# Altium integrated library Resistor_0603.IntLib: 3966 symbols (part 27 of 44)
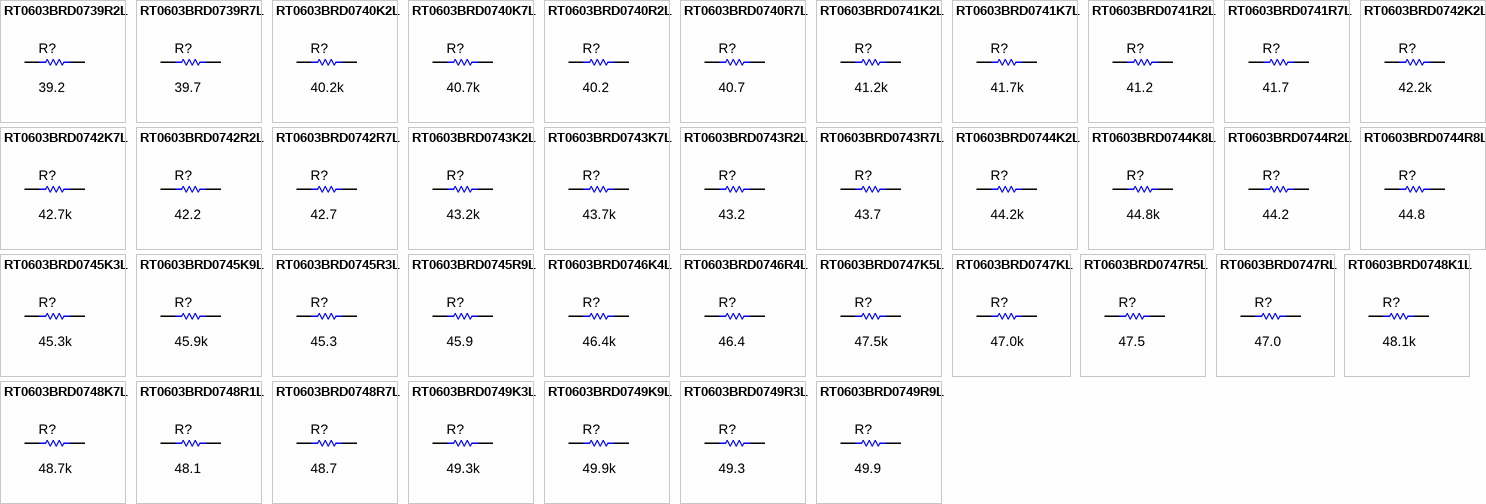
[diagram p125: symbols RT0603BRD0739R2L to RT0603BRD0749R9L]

## RT0603BRD0749R9L
designator R?  ValueDisplayed: 49.9  (hidden comment: RT0603BRD0749R9L)
RES, 49.9, 0.1%, 0.1 W, 0603; Manufacturer: Yageo America; CompType: Resistor; Value: 49.9; Value_Code: 49R9; Tolerance_%: 0.1; Value2: 0.1W; VDC_V: 75; TempCo: 25 ppm/C; SizeArea_mm2: 1.28; SizeX_mm: 1.6; SizeY_mm: 0.8; SizeZ_mm: 1; EIA_Code: E192; U/M: EA; AEC Category: Q200
signal-integrity model Resistor
simulation model Resistor
footprint 0603
footprint 0603M
footprint 0603L
footprint 0603_HV
footprint 0603S
pins: 1, 2

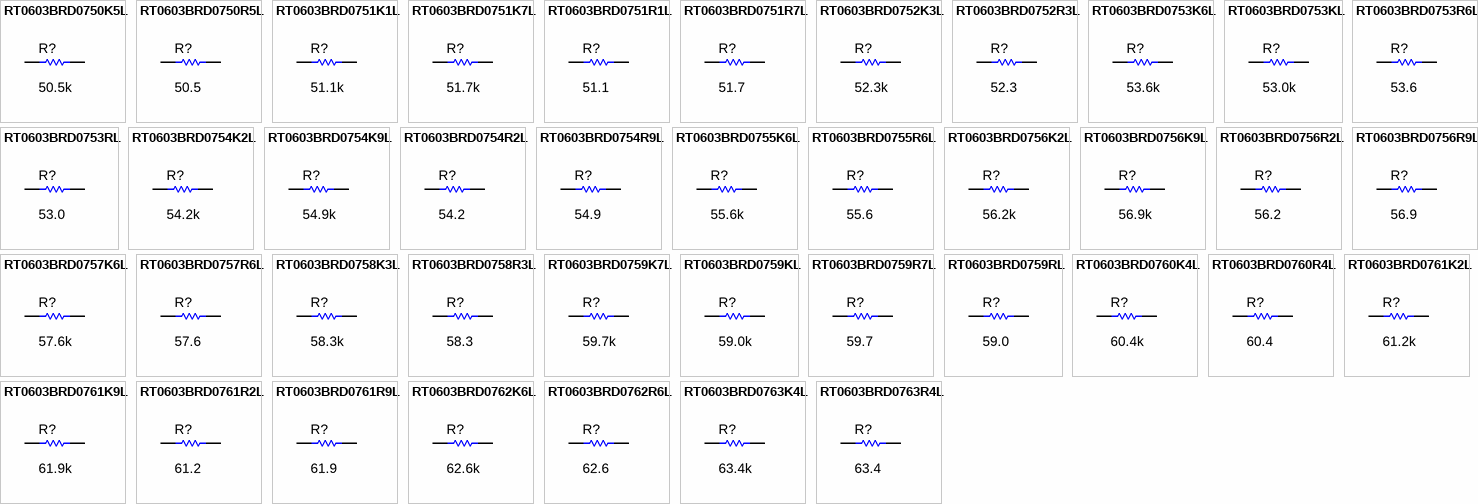
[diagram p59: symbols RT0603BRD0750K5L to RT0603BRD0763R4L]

## RT0603BRD0750K5L
designator R?  ValueDisplayed: 50.5k  (hidden comment: RT0603BRD0750K5L)
RES, 50.5 k, 0.1%, 0.1 W, 0603; Manufacturer: Yageo America; CompType: Resistor; Value: 50.5k; Res_ohm: 50500; Value_Code: 50k5; Tolerance_%: 0.1; Value2: 0.1W; VDC_V: 75; TempCo: 25 ppm/C; SizeArea_mm2: 1.28; SizeX_mm: 1.6; SizeY_mm: 0.8; SizeZ_mm: 1; EIA_Code: E192; U/M: EA; AEC Category: Q200
signal-integrity model Resistor
simulation model Resistor
footprint 0603
footprint 0603M
footprint 0603L
footprint 0603_HV
footprint 0603S
pins: 1, 2

## RT0603BRD0750R5L
designator R?  ValueDisplayed: 50.5  (hidden comment: RT0603BRD0750R5L)
RES, 50.5, 0.1%, 0.1 W, 0603; Manufacturer: Yageo America; CompType: Resistor; Value: 50.5; Value_Code: 50R5; Tolerance_%: 0.1; Value2: 0.1W; VDC_V: 75; TempCo: 25 ppm/C; SizeArea_mm2: 1.28; SizeX_mm: 1.6; SizeY_mm: 0.8; SizeZ_mm: 1; EIA_Code: E192; U/M: EA; AEC Category: Q200
signal-integrity model Resistor
simulation model Resistor
footprint 0603
footprint 0603M
footprint 0603L
footprint 0603_HV
footprint 0603S
pins: 1, 2

## RT0603BRD0751K1L
designator R?  ValueDisplayed: 51.1k  (hidden comment: RT0603BRD0751K1L)
RES, 51.1 k, 0.1%, 0.1 W, 0603; Manufacturer: Yageo America; CompType: Resistor; Value: 51.1k; Res_ohm: 51100; Value_Code: 51k1; Tolerance_%: 0.1; Value2: 0.1W; VDC_V: 75; TempCo: 25 ppm/C; SizeArea_mm2: 1.28; SizeX_mm: 1.6; SizeY_mm: 0.8; SizeZ_mm: 1; EIA_Code: E192; U/M: EA; AEC Category: Q200
signal-integrity model Resistor
simulation model Resistor
footprint 0603
footprint 0603M
footprint 0603L
footprint 0603_HV
footprint 0603S
pins: 1, 2

## RT0603BRD0751K7L
designator R?  ValueDisplayed: 51.7k  (hidden comment: RT0603BRD0751K7L)
RES, 51.7 k, 0.1%, 0.1 W, 0603; Manufacturer: Yageo America; CompType: Resistor; Value: 51.7k; Res_ohm: 51700; Value_Code: 51k7; Tolerance_%: 0.1; Value2: 0.1W; VDC_V: 75; TempCo: 25 ppm/C; SizeArea_mm2: 1.28; SizeX_mm: 1.6; SizeY_mm: 0.8; SizeZ_mm: 1; EIA_Code: E192; U/M: EA; AEC Category: Q200
signal-integrity model Resistor
simulation model Resistor
footprint 0603
footprint 0603M
footprint 0603L
footprint 0603_HV
footprint 0603S
pins: 1, 2

## RT0603BRD0751R1L
designator R?  ValueDisplayed: 51.1  (hidden comment: RT0603BRD0751R1L)
RES, 51.1, 0.1%, 0.1 W, 0603; Manufacturer: Yageo America; CompType: Resistor; Value: 51.1; Value_Code: 51R1; Tolerance_%: 0.1; Value2: 0.1W; VDC_V: 75; TempCo: 25 ppm/C; SizeArea_mm2: 1.28; SizeX_mm: 1.6; SizeY_mm: 0.8; SizeZ_mm: 1; EIA_Code: E192; U/M: EA; AEC Category: Q200; Green_Lifecycle: Active; Green_REACh: Passed
signal-integrity model Resistor
simulation model Resistor
footprint 0603
footprint 0603M
footprint 0603L
footprint 0603_HV
footprint 0603S
pins: 1, 2

## RT0603BRD0751R7L
designator R?  ValueDisplayed: 51.7  (hidden comment: RT0603BRD0751R7L)
RES, 51.7, 0.1%, 0.1 W, 0603; Manufacturer: Yageo America; CompType: Resistor; Value: 51.7; Value_Code: 51R7; Tolerance_%: 0.1; Value2: 0.1W; VDC_V: 75; TempCo: 25 ppm/C; SizeArea_mm2: 1.28; SizeX_mm: 1.6; SizeY_mm: 0.8; SizeZ_mm: 1; EIA_Code: E192; U/M: EA; AEC Category: Q200
signal-integrity model Resistor
simulation model Resistor
footprint 0603
footprint 0603M
footprint 0603L
footprint 0603_HV
footprint 0603S
pins: 1, 2

## RT0603BRD0752K3L
designator R?  ValueDisplayed: 52.3k  (hidden comment: RT0603BRD0752K3L)
RES, 52.3 k, 0.1%, 0.1 W, 0603; Manufacturer: Yageo America; CompType: Resistor; Value: 52.3k; Res_ohm: 52300; Value_Code: 52k3; Tolerance_%: 0.1; Value2: 0.1W; VDC_V: 75; TempCo: 25 ppm/C; SizeArea_mm2: 1.28; SizeX_mm: 1.6; SizeY_mm: 0.8; SizeZ_mm: 1; EIA_Code: E192; U/M: EA; AEC Category: Q200
signal-integrity model Resistor
simulation model Resistor
footprint 0603
footprint 0603M
footprint 0603L
footprint 0603_HV
footprint 0603S
pins: 1, 2

## RT0603BRD0752R3L
designator R?  ValueDisplayed: 52.3  (hidden comment: RT0603BRD0752R3L)
RES, 52.3, 0.1%, 0.1 W, 0603; Manufacturer: Yageo America; CompType: Resistor; Value: 52.3; Value_Code: 52R3; Tolerance_%: 0.1; Value2: 0.1W; VDC_V: 75; TempCo: 25 ppm/C; SizeArea_mm2: 1.28; SizeX_mm: 1.6; SizeY_mm: 0.8; SizeZ_mm: 1; EIA_Code: E192; U/M: EA; AEC Category: Q200
signal-integrity model Resistor
simulation model Resistor
footprint 0603
footprint 0603M
footprint 0603L
footprint 0603_HV
footprint 0603S
pins: 1, 2

## RT0603BRD0753K6L
designator R?  ValueDisplayed: 53.6k  (hidden comment: RT0603BRD0753K6L)
RES, 53.6 k, 0.1%, 0.1 W, 0603; Manufacturer: Yageo America; CompType: Resistor; Value: 53.6k; Res_ohm: 53600; Value_Code: 53k6; Tolerance_%: 0.1; Value2: 0.1W; VDC_V: 75; TempCo: 25 ppm/C; SizeArea_mm2: 1.28; SizeX_mm: 1.6; SizeY_mm: 0.8; SizeZ_mm: 1; EIA_Code: E192; U/M: EA; AEC Category: Q200
signal-integrity model Resistor
simulation model Resistor
footprint 0603
footprint 0603M
footprint 0603L
footprint 0603_HV
footprint 0603S
pins: 1, 2

## RT0603BRD0753KL
designator R?  ValueDisplayed: 53.0k  (hidden comment: RT0603BRD0753KL)
RES, 53.0 k, 0.1%, 0.1 W, 0603; Manufacturer: Yageo America; CompType: Resistor; Value: 53.0k; Res_ohm: 53000; Value_Code: 53k0; Tolerance_%: 0.1; Value2: 0.1W; VDC_V: 75; TempCo: 25 ppm/C; SizeArea_mm2: 1.28; SizeX_mm: 1.6; SizeY_mm: 0.8; SizeZ_mm: 1; EIA_Code: E192; U/M: EA; AEC Category: Q200
signal-integrity model Resistor
simulation model Resistor
footprint 0603
footprint 0603M
footprint 0603L
footprint 0603_HV
footprint 0603S
pins: 1, 2

## RT0603BRD0753R6L
designator R?  ValueDisplayed: 53.6  (hidden comment: RT0603BRD0753R6L)
RES, 53.6, 0.1%, 0.1 W, 0603; Manufacturer: Yageo America; CompType: Resistor; Value: 53.6; Value_Code: 53R6; Tolerance_%: 0.1; Value2: 0.1W; VDC_V: 75; TempCo: 25 ppm/C; SizeArea_mm2: 1.28; SizeX_mm: 1.6; SizeY_mm: 0.8; SizeZ_mm: 1; EIA_Code: E192; U/M: EA; AEC Category: Q200
signal-integrity model Resistor
simulation model Resistor
footprint 0603
footprint 0603M
footprint 0603L
footprint 0603_HV
footprint 0603S
pins: 1, 2

## RT0603BRD0753RL
designator R?  ValueDisplayed: 53.0  (hidden comment: RT0603BRD0753RL)
RES, 53.0, 0.1%, 0.1 W, 0603; Manufacturer: Yageo America; CompType: Resistor; Value: 53.0; Res_ohm: 53; Value_Code: 53R0; Tolerance_%: 0.1; Value2: 0.1W; VDC_V: 75; TempCo: 25 ppm/C; SizeArea_mm2: 1.28; SizeX_mm: 1.6; SizeY_mm: 0.8; SizeZ_mm: 1; EIA_Code: E192; U/M: EA; AEC Category: Q200
signal-integrity model Resistor
simulation model Resistor
footprint 0603
footprint 0603M
footprint 0603L
footprint 0603_HV
footprint 0603S
pins: 1, 2

## RT0603BRD0754K2L
designator R?  ValueDisplayed: 54.2k  (hidden comment: RT0603BRD0754K2L)
RES, 54.2 k, 0.1%, 0.1 W, 0603; Manufacturer: Yageo America; CompType: Resistor; Value: 54.2k; Res_ohm: 54200; Value_Code: 54k2; Tolerance_%: 0.1; Value2: 0.1W; VDC_V: 75; TempCo: 25 ppm/C; SizeArea_mm2: 1.28; SizeX_mm: 1.6; SizeY_mm: 0.8; SizeZ_mm: 1; EIA_Code: E192; U/M: EA; AEC Category: Q200
signal-integrity model Resistor
simulation model Resistor
footprint 0603
footprint 0603M
footprint 0603L
footprint 0603_HV
footprint 0603S
pins: 1, 2

## RT0603BRD0754K9L
designator R?  ValueDisplayed: 54.9k  (hidden comment: RT0603BRD0754K9L)
RES, 54.9 k, 0.1%, 0.1 W, 0603; Manufacturer: Yageo America; CompType: Resistor; Value: 54.9k; Res_ohm: 54900; Value_Code: 54k9; Tolerance_%: 0.1; Value2: 0.1W; VDC_V: 75; TempCo: 25 ppm/C; SizeArea_mm2: 1.28; SizeX_mm: 1.6; SizeY_mm: 0.8; SizeZ_mm: 1; EIA_Code: E192; U/M: EA; AEC Category: Q200
signal-integrity model Resistor
simulation model Resistor
footprint 0603
footprint 0603M
footprint 0603L
footprint 0603_HV
footprint 0603S
pins: 1, 2

## RT0603BRD0754R2L
designator R?  ValueDisplayed: 54.2  (hidden comment: RT0603BRD0754R2L)
RES, 54.2, 0.1%, 0.1 W, 0603; Manufacturer: Yageo America; CompType: Resistor; Value: 54.2; Value_Code: 54R2; Tolerance_%: 0.1; Value2: 0.1W; VDC_V: 75; TempCo: 25 ppm/C; SizeArea_mm2: 1.28; SizeX_mm: 1.6; SizeY_mm: 0.8; SizeZ_mm: 1; EIA_Code: E192; U/M: EA; AEC Category: Q200
signal-integrity model Resistor
simulation model Resistor
footprint 0603
footprint 0603M
footprint 0603L
footprint 0603_HV
footprint 0603S
pins: 1, 2

## RT0603BRD0754R9L
designator R?  ValueDisplayed: 54.9  (hidden comment: RT0603BRD0754R9L)
RES, 54.9, 0.1%, 0.1 W, 0603; Manufacturer: Yageo America; CompType: Resistor; Value: 54.9; Value_Code: 54R9; Tolerance_%: 0.1; Value2: 0.1W; VDC_V: 75; TempCo: 25 ppm/C; SizeArea_mm2: 1.28; SizeX_mm: 1.6; SizeY_mm: 0.8; SizeZ_mm: 1; EIA_Code: E192; U/M: EA; AEC Category: Q200
signal-integrity model Resistor
simulation model Resistor
footprint 0603
footprint 0603M
footprint 0603L
footprint 0603_HV
footprint 0603S
pins: 1, 2

## RT0603BRD0755K6L
designator R?  ValueDisplayed: 55.6k  (hidden comment: RT0603BRD0755K6L)
RES, 55.6 k, 0.1%, 0.1 W, 0603; Manufacturer: Yageo America; CompType: Resistor; Value: 55.6k; Res_ohm: 55600; Value_Code: 55k6; Tolerance_%: 0.1; Value2: 0.1W; VDC_V: 75; TempCo: 25 ppm/C; SizeArea_mm2: 1.28; SizeX_mm: 1.6; SizeY_mm: 0.8; SizeZ_mm: 1; EIA_Code: E192; U/M: EA; AEC Category: Q200
signal-integrity model Resistor
simulation model Resistor
footprint 0603
footprint 0603M
footprint 0603L
footprint 0603_HV
footprint 0603S
pins: 1, 2

## RT0603BRD0755R6L
designator R?  ValueDisplayed: 55.6  (hidden comment: RT0603BRD0755R6L)
RES, 55.6, 0.1%, 0.1 W, 0603; Manufacturer: Yageo America; CompType: Resistor; Value: 55.6; Value_Code: 55R6; Tolerance_%: 0.1; Value2: 0.1W; VDC_V: 75; TempCo: 25 ppm/C; SizeArea_mm2: 1.28; SizeX_mm: 1.6; SizeY_mm: 0.8; SizeZ_mm: 1; EIA_Code: E192; U/M: EA; AEC Category: Q200
signal-integrity model Resistor
simulation model Resistor
footprint 0603
footprint 0603M
footprint 0603L
footprint 0603_HV
footprint 0603S
pins: 1, 2

## RT0603BRD0756K2L
designator R?  ValueDisplayed: 56.2k  (hidden comment: RT0603BRD0756K2L)
RES, 56.2 k, 0.1%, 0.1 W, 0603; Manufacturer: Yageo America; CompType: Resistor; Value: 56.2k; Res_ohm: 56200; Value_Code: 56k2; Tolerance_%: 0.1; Value2: 0.1W; VDC_V: 75; TempCo: 25 ppm/C; SizeArea_mm2: 1.28; SizeX_mm: 1.6; SizeY_mm: 0.8; SizeZ_mm: 1; EIA_Code: E192; U/M: EA; AEC Category: Q200
signal-integrity model Resistor
simulation model Resistor
footprint 0603
footprint 0603M
footprint 0603L
footprint 0603_HV
footprint 0603S
pins: 1, 2

## RT0603BRD0756K9L
designator R?  ValueDisplayed: 56.9k  (hidden comment: RT0603BRD0756K9L)
RES, 56.9 k, 0.1%, 0.1 W, 0603; Manufacturer: Yageo America; CompType: Resistor; Value: 56.9k; Res_ohm: 56900; Value_Code: 56k9; Tolerance_%: 0.1; Value2: 0.1W; VDC_V: 75; TempCo: 25 ppm/C; SizeArea_mm2: 1.28; SizeX_mm: 1.6; SizeY_mm: 0.8; SizeZ_mm: 1; EIA_Code: E192; U/M: EA; AEC Category: Q200
signal-integrity model Resistor
simulation model Resistor
footprint 0603
footprint 0603M
footprint 0603L
footprint 0603_HV
footprint 0603S
pins: 1, 2

## RT0603BRD0756R2L
designator R?  ValueDisplayed: 56.2  (hidden comment: RT0603BRD0756R2L)
RES, 56.2, 0.1%, 0.1 W, 0603; Manufacturer: Yageo America; CompType: Resistor; Value: 56.2; Value_Code: 56R2; Tolerance_%: 0.1; Value2: 0.1W; VDC_V: 75; TempCo: 25 ppm/C; SizeArea_mm2: 1.28; SizeX_mm: 1.6; SizeY_mm: 0.8; SizeZ_mm: 1; EIA_Code: E192; U/M: EA; AEC Category: Q200
signal-integrity model Resistor
simulation model Resistor
footprint 0603
footprint 0603M
footprint 0603L
footprint 0603_HV
footprint 0603S
pins: 1, 2

## RT0603BRD0756R9L
designator R?  ValueDisplayed: 56.9  (hidden comment: RT0603BRD0756R9L)
RES, 56.9, 0.1%, 0.1 W, 0603; Manufacturer: Yageo America; CompType: Resistor; Value: 56.9; Value_Code: 56R9; Tolerance_%: 0.1; Value2: 0.1W; VDC_V: 75; TempCo: 25 ppm/C; SizeArea_mm2: 1.28; SizeX_mm: 1.6; SizeY_mm: 0.8; SizeZ_mm: 1; EIA_Code: E192; U/M: EA; AEC Category: Q200
signal-integrity model Resistor
simulation model Resistor
footprint 0603
footprint 0603M
footprint 0603L
footprint 0603_HV
footprint 0603S
pins: 1, 2

## RT0603BRD0757K6L
designator R?  ValueDisplayed: 57.6k  (hidden comment: RT0603BRD0757K6L)
RES, 57.6 k, 0.1%, 0.1 W, 0603; Manufacturer: Yageo America; CompType: Resistor; Value: 57.6k; Res_ohm: 57600; Value_Code: 57k6; Tolerance_%: 0.1; Value2: 0.1W; VDC_V: 75; TempCo: 25 ppm/C; SizeArea_mm2: 1.28; SizeX_mm: 1.6; SizeY_mm: 0.8; SizeZ_mm: 1; EIA_Code: E192; U/M: EA; AEC Category: Q200
signal-integrity model Resistor
simulation model Resistor
footprint 0603
footprint 0603M
footprint 0603L
footprint 0603_HV
footprint 0603S
pins: 1, 2

## RT0603BRD0757R6L
designator R?  ValueDisplayed: 57.6  (hidden comment: RT0603BRD0757R6L)
RES, 57.6, 0.1%, 0.1 W, 0603; Manufacturer: Yageo America; CompType: Resistor; Value: 57.6; Value_Code: 57R6; Tolerance_%: 0.1; Value2: 0.1W; VDC_V: 75; TempCo: 25 ppm/C; SizeArea_mm2: 1.28; SizeX_mm: 1.6; SizeY_mm: 0.8; SizeZ_mm: 1; EIA_Code: E192; U/M: EA; AEC Category: Q200
signal-integrity model Resistor
simulation model Resistor
footprint 0603
footprint 0603M
footprint 0603L
footprint 0603_HV
footprint 0603S
pins: 1, 2

## RT0603BRD0758K3L
designator R?  ValueDisplayed: 58.3k  (hidden comment: RT0603BRD0758K3L)
RES, 58.3 k, 0.1%, 0.1 W, 0603; Manufacturer: Yageo America; CompType: Resistor; Value: 58.3k; Res_ohm: 58300; Value_Code: 58k3; Tolerance_%: 0.1; Value2: 0.1W; VDC_V: 75; TempCo: 25 ppm/C; SizeArea_mm2: 1.28; SizeX_mm: 1.6; SizeY_mm: 0.8; SizeZ_mm: 1; EIA_Code: E192; U/M: EA; AEC Category: Q200
signal-integrity model Resistor
simulation model Resistor
footprint 0603
footprint 0603M
footprint 0603L
footprint 0603_HV
footprint 0603S
pins: 1, 2

## RT0603BRD0758R3L
designator R?  ValueDisplayed: 58.3  (hidden comment: RT0603BRD0758R3L)
RES, 58.3, 0.1%, 0.1 W, 0603; Manufacturer: Yageo America; CompType: Resistor; Value: 58.3; Value_Code: 58R3; Tolerance_%: 0.1; Value2: 0.1W; VDC_V: 75; TempCo: 25 ppm/C; SizeArea_mm2: 1.28; SizeX_mm: 1.6; SizeY_mm: 0.8; SizeZ_mm: 1; EIA_Code: E192; U/M: EA; AEC Category: Q200
signal-integrity model Resistor
simulation model Resistor
footprint 0603
footprint 0603M
footprint 0603L
footprint 0603_HV
footprint 0603S
pins: 1, 2

## RT0603BRD0759K7L
designator R?  ValueDisplayed: 59.7k  (hidden comment: RT0603BRD0759K7L)
RES, 59.7 k, 0.1%, 0.1 W, 0603; Manufacturer: Yageo America; CompType: Resistor; Value: 59.7k; Res_ohm: 59700; Value_Code: 59k7; Tolerance_%: 0.1; Value2: 0.1W; VDC_V: 75; TempCo: 25 ppm/C; SizeArea_mm2: 1.28; SizeX_mm: 1.6; SizeY_mm: 0.8; SizeZ_mm: 1; EIA_Code: E192; U/M: EA; AEC Category: Q200
signal-integrity model Resistor
simulation model Resistor
footprint 0603
footprint 0603M
footprint 0603L
footprint 0603_HV
footprint 0603S
pins: 1, 2

## RT0603BRD0759KL
designator R?  ValueDisplayed: 59.0k  (hidden comment: RT0603BRD0759KL)
RES, 59.0 k, 0.1%, 0.1 W, 0603; Manufacturer: Yageo America; CompType: Resistor; Value: 59.0k; Res_ohm: 59000; Value_Code: 59k0; Tolerance_%: 0.1; Value2: 0.1W; VDC_V: 75; TempCo: 25 ppm/C; SizeArea_mm2: 1.28; SizeX_mm: 1.6; SizeY_mm: 0.8; SizeZ_mm: 1; EIA_Code: E192; U/M: EA; AEC Category: Q200
signal-integrity model Resistor
simulation model Resistor
footprint 0603
footprint 0603M
footprint 0603L
footprint 0603_HV
footprint 0603S
pins: 1, 2

## RT0603BRD0759R7L
designator R?  ValueDisplayed: 59.7  (hidden comment: RT0603BRD0759R7L)
RES, 59.7, 0.1%, 0.1 W, 0603; Manufacturer: Yageo America; CompType: Resistor; Value: 59.7; Value_Code: 59R7; Tolerance_%: 0.1; Value2: 0.1W; VDC_V: 75; TempCo: 25 ppm/C; SizeArea_mm2: 1.28; SizeX_mm: 1.6; SizeY_mm: 0.8; SizeZ_mm: 1; EIA_Code: E192; U/M: EA; AEC Category: Q200
signal-integrity model Resistor
simulation model Resistor
footprint 0603
footprint 0603M
footprint 0603L
footprint 0603_HV
footprint 0603S
pins: 1, 2

## RT0603BRD0759RL
designator R?  ValueDisplayed: 59.0  (hidden comment: RT0603BRD0759RL)
RES, 59.0, 0.1%, 0.1 W, 0603; Manufacturer: Yageo America; CompType: Resistor; Value: 59.0; Res_ohm: 59; Value_Code: 59R0; Tolerance_%: 0.1; Value2: 0.1W; VDC_V: 75; TempCo: 25 ppm/C; SizeArea_mm2: 1.28; SizeX_mm: 1.6; SizeY_mm: 0.8; SizeZ_mm: 1; EIA_Code: E192; U/M: EA; AEC Category: Q200
signal-integrity model Resistor
simulation model Resistor
footprint 0603
footprint 0603M
footprint 0603L
footprint 0603_HV
footprint 0603S
pins: 1, 2

## RT0603BRD0760K4L
designator R?  ValueDisplayed: 60.4k  (hidden comment: RT0603BRD0760K4L)
RES, 60.4 k, 0.1%, 0.1 W, 0603; Manufacturer: Yageo America; CompType: Resistor; Value: 60.4k; Res_ohm: 60400; Value_Code: 60k4; Tolerance_%: 0.1; Value2: 0.1W; VDC_V: 75; TempCo: 25 ppm/C; SizeArea_mm2: 1.28; SizeX_mm: 1.6; SizeY_mm: 0.8; SizeZ_mm: 1; EIA_Code: E192; U/M: EA; AEC Category: Q200
signal-integrity model Resistor
simulation model Resistor
footprint 0603
footprint 0603M
footprint 0603L
footprint 0603_HV
footprint 0603S
pins: 1, 2

## RT0603BRD0760R4L
designator R?  ValueDisplayed: 60.4  (hidden comment: RT0603BRD0760R4L)
RES, 60.4, 0.1%, 0.1 W, 0603; Manufacturer: Yageo America; CompType: Resistor; Value: 60.4; Value_Code: 60R4; Tolerance_%: 0.1; Value2: 0.1W; VDC_V: 75; TempCo: 25 ppm/C; SizeArea_mm2: 1.28; SizeX_mm: 1.6; SizeY_mm: 0.8; SizeZ_mm: 1; EIA_Code: E192; U/M: EA; AEC Category: Q200
signal-integrity model Resistor
simulation model Resistor
footprint 0603
footprint 0603M
footprint 0603L
footprint 0603_HV
footprint 0603S
pins: 1, 2

## RT0603BRD0761K2L
designator R?  ValueDisplayed: 61.2k  (hidden comment: RT0603BRD0761K2L)
RES, 61.2 k, 0.1%, 0.1 W, 0603; Manufacturer: Yageo America; CompType: Resistor; Value: 61.2k; Res_ohm: 61200; Value_Code: 61k2; Tolerance_%: 0.1; Value2: 0.1W; VDC_V: 75; TempCo: 25 ppm/C; SizeArea_mm2: 1.28; SizeX_mm: 1.6; SizeY_mm: 0.8; SizeZ_mm: 1; EIA_Code: E192; U/M: EA; AEC Category: Q200
signal-integrity model Resistor
simulation model Resistor
footprint 0603
footprint 0603M
footprint 0603L
footprint 0603_HV
footprint 0603S
pins: 1, 2

## RT0603BRD0761K9L
designator R?  ValueDisplayed: 61.9k  (hidden comment: RT0603BRD0761K9L)
RES, 61.9 k, 0.1%, 0.1 W, 0603; Manufacturer: Yageo America; CompType: Resistor; Value: 61.9k; Res_ohm: 61900; Value_Code: 61k9; Tolerance_%: 0.1; Value2: 0.1W; VDC_V: 75; TempCo: 25 ppm/C; SizeArea_mm2: 1.28; SizeX_mm: 1.6; SizeY_mm: 0.8; SizeZ_mm: 1; EIA_Code: E192; U/M: EA; AEC Category: Q200
signal-integrity model Resistor
simulation model Resistor
footprint 0603
footprint 0603M
footprint 0603L
footprint 0603_HV
footprint 0603S
pins: 1, 2

## RT0603BRD0761R2L
designator R?  ValueDisplayed: 61.2  (hidden comment: RT0603BRD0761R2L)
RES, 61.2, 0.1%, 0.1 W, 0603; Manufacturer: Yageo America; CompType: Resistor; Value: 61.2; Value_Code: 61R2; Tolerance_%: 0.1; Value2: 0.1W; VDC_V: 75; TempCo: 25 ppm/C; SizeArea_mm2: 1.28; SizeX_mm: 1.6; SizeY_mm: 0.8; SizeZ_mm: 1; EIA_Code: E192; U/M: EA; AEC Category: Q200
signal-integrity model Resistor
simulation model Resistor
footprint 0603
footprint 0603M
footprint 0603L
footprint 0603_HV
footprint 0603S
pins: 1, 2

## RT0603BRD0761R9L
designator R?  ValueDisplayed: 61.9  (hidden comment: RT0603BRD0761R9L)
RES, 61.9, 0.1%, 0.1 W, 0603; Manufacturer: Yageo America; CompType: Resistor; Value: 61.9; Value_Code: 61R9; Tolerance_%: 0.1; Value2: 0.1W; VDC_V: 75; TempCo: 25 ppm/C; SizeArea_mm2: 1.28; SizeX_mm: 1.6; SizeY_mm: 0.8; SizeZ_mm: 1; EIA_Code: E192; U/M: EA; AEC Category: Q200
signal-integrity model Resistor
simulation model Resistor
footprint 0603
footprint 0603M
footprint 0603L
footprint 0603_HV
footprint 0603S
pins: 1, 2

## RT0603BRD0762K6L
designator R?  ValueDisplayed: 62.6k  (hidden comment: RT0603BRD0762K6L)
RES, 62.6 k, 0.1%, 0.1 W, 0603; Manufacturer: Yageo America; CompType: Resistor; Value: 62.6k; Res_ohm: 62600; Value_Code: 62k6; Tolerance_%: 0.1; Value2: 0.1W; VDC_V: 75; TempCo: 25 ppm/C; SizeArea_mm2: 1.28; SizeX_mm: 1.6; SizeY_mm: 0.8; SizeZ_mm: 1; EIA_Code: E192; U/M: EA; AEC Category: Q200
signal-integrity model Resistor
simulation model Resistor
footprint 0603
footprint 0603M
footprint 0603L
footprint 0603_HV
footprint 0603S
pins: 1, 2

## RT0603BRD0762R6L
designator R?  ValueDisplayed: 62.6  (hidden comment: RT0603BRD0762R6L)
RES, 62.6, 0.1%, 0.1 W, 0603; Manufacturer: Yageo America; CompType: Resistor; Value: 62.6; Value_Code: 62R6; Tolerance_%: 0.1; Value2: 0.1W; VDC_V: 75; TempCo: 25 ppm/C; SizeArea_mm2: 1.28; SizeX_mm: 1.6; SizeY_mm: 0.8; SizeZ_mm: 1; EIA_Code: E192; U/M: EA; AEC Category: Q200
signal-integrity model Resistor
simulation model Resistor
footprint 0603
footprint 0603M
footprint 0603L
footprint 0603_HV
footprint 0603S
pins: 1, 2

## RT0603BRD0763K4L
designator R?  ValueDisplayed: 63.4k  (hidden comment: RT0603BRD0763K4L)
RES, 63.4 k, 0.1%, 0.1 W, 0603; Manufacturer: Yageo America; CompType: Resistor; Value: 63.4k; Res_ohm: 63400; Value_Code: 63k4; Tolerance_%: 0.1; Value2: 0.1W; VDC_V: 75; TempCo: 25 ppm/C; SizeArea_mm2: 1.28; SizeX_mm: 1.6; SizeY_mm: 0.8; SizeZ_mm: 1; EIA_Code: E192; U/M: EA; AEC Category: Q200
signal-integrity model Resistor
simulation model Resistor
footprint 0603
footprint 0603M
footprint 0603L
footprint 0603_HV
footprint 0603S
pins: 1, 2

## RT0603BRD0763R4L
designator R?  ValueDisplayed: 63.4  (hidden comment: RT0603BRD0763R4L)
RES, 63.4, 0.1%, 0.1 W, 0603; Manufacturer: Yageo America; CompType: Resistor; Value: 63.4; Value_Code: 63R4; Tolerance_%: 0.1; Value2: 0.1W; VDC_V: 75; TempCo: 25 ppm/C; SizeArea_mm2: 1.28; SizeX_mm: 1.6; SizeY_mm: 0.8; SizeZ_mm: 1; EIA_Code: E192; U/M: EA; AEC Category: Q200
signal-integrity model Resistor
simulation model Resistor
footprint 0603
footprint 0603M
footprint 0603L
footprint 0603_HV
footprint 0603S
pins: 1, 2

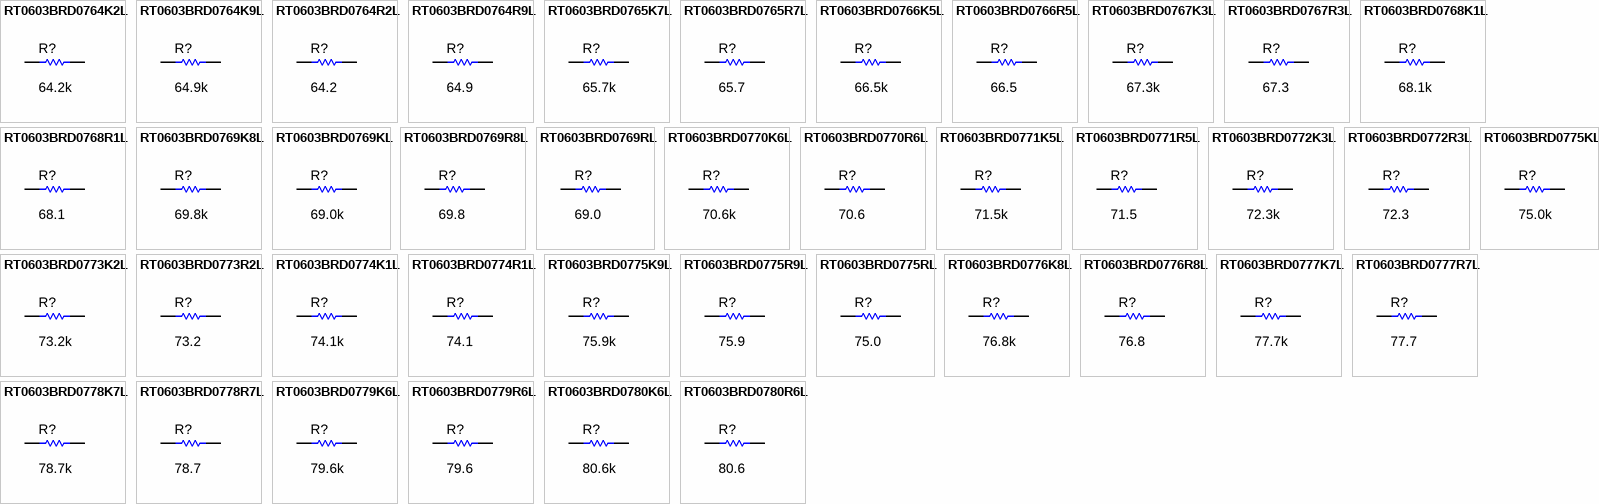
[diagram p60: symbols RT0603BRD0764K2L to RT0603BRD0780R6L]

## RT0603BRD0764K2L
designator R?  ValueDisplayed: 64.2k  (hidden comment: RT0603BRD0764K2L)
RES, 64.2 k, 0.1%, 0.1 W, 0603; Manufacturer: Yageo America; CompType: Resistor; Value: 64.2k; Res_ohm: 64200; Value_Code: 64k2; Tolerance_%: 0.1; Value2: 0.1W; VDC_V: 75; TempCo: 25 ppm/C; SizeArea_mm2: 1.28; SizeX_mm: 1.6; SizeY_mm: 0.8; SizeZ_mm: 1; EIA_Code: E192; U/M: EA; AEC Category: Q200
signal-integrity model Resistor
simulation model Resistor
footprint 0603
footprint 0603M
footprint 0603L
footprint 0603_HV
footprint 0603S
pins: 1, 2

## RT0603BRD0764K9L
designator R?  ValueDisplayed: 64.9k  (hidden comment: RT0603BRD0764K9L)
RES, 64.9 k, 0.1%, 0.1 W, 0603; Manufacturer: Yageo America; CompType: Resistor; Value: 64.9k; Res_ohm: 64900; Value_Code: 64k9; Tolerance_%: 0.1; Value2: 0.1W; VDC_V: 75; TempCo: 25 ppm/C; SizeArea_mm2: 1.28; SizeX_mm: 1.6; SizeY_mm: 0.8; SizeZ_mm: 1; EIA_Code: E192; U/M: EA; AEC Category: Q200
signal-integrity model Resistor
simulation model Resistor
footprint 0603
footprint 0603M
footprint 0603L
footprint 0603_HV
footprint 0603S
pins: 1, 2

## RT0603BRD0764R2L
designator R?  ValueDisplayed: 64.2  (hidden comment: RT0603BRD0764R2L)
RES, 64.2, 0.1%, 0.1 W, 0603; Manufacturer: Yageo America; CompType: Resistor; Value: 64.2; Value_Code: 64R2; Tolerance_%: 0.1; Value2: 0.1W; VDC_V: 75; TempCo: 25 ppm/C; SizeArea_mm2: 1.28; SizeX_mm: 1.6; SizeY_mm: 0.8; SizeZ_mm: 1; EIA_Code: E192; U/M: EA; AEC Category: Q200
signal-integrity model Resistor
simulation model Resistor
footprint 0603
footprint 0603M
footprint 0603L
footprint 0603_HV
footprint 0603S
pins: 1, 2

## RT0603BRD0764R9L
designator R?  ValueDisplayed: 64.9  (hidden comment: RT0603BRD0764R9L)
RES, 64.9, 0.1%, 0.1 W, 0603; Manufacturer: Yageo America; CompType: Resistor; Value: 64.9; Value_Code: 64R9; Tolerance_%: 0.1; Value2: 0.1W; VDC_V: 75; TempCo: 25 ppm/C; SizeArea_mm2: 1.28; SizeX_mm: 1.6; SizeY_mm: 0.8; SizeZ_mm: 1; EIA_Code: E192; U/M: EA; AEC Category: Q200
signal-integrity model Resistor
simulation model Resistor
footprint 0603
footprint 0603M
footprint 0603L
footprint 0603_HV
footprint 0603S
pins: 1, 2

## RT0603BRD0765K7L
designator R?  ValueDisplayed: 65.7k  (hidden comment: RT0603BRD0765K7L)
RES, 65.7 k, 0.1%, 0.1 W, 0603; Manufacturer: Yageo America; CompType: Resistor; Value: 65.7k; Res_ohm: 65700; Value_Code: 65k7; Tolerance_%: 0.1; Value2: 0.1W; VDC_V: 75; TempCo: 25 ppm/C; SizeArea_mm2: 1.28; SizeX_mm: 1.6; SizeY_mm: 0.8; SizeZ_mm: 1; EIA_Code: E192; U/M: EA; AEC Category: Q200
signal-integrity model Resistor
simulation model Resistor
footprint 0603
footprint 0603M
footprint 0603L
footprint 0603_HV
footprint 0603S
pins: 1, 2

## RT0603BRD0765R7L
designator R?  ValueDisplayed: 65.7  (hidden comment: RT0603BRD0765R7L)
RES, 65.7, 0.1%, 0.1 W, 0603; Manufacturer: Yageo America; CompType: Resistor; Value: 65.7; Value_Code: 65R7; Tolerance_%: 0.1; Value2: 0.1W; VDC_V: 75; TempCo: 25 ppm/C; SizeArea_mm2: 1.28; SizeX_mm: 1.6; SizeY_mm: 0.8; SizeZ_mm: 1; EIA_Code: E192; U/M: EA; AEC Category: Q200
signal-integrity model Resistor
simulation model Resistor
footprint 0603
footprint 0603M
footprint 0603L
footprint 0603_HV
footprint 0603S
pins: 1, 2

## RT0603BRD0766K5L
designator R?  ValueDisplayed: 66.5k  (hidden comment: RT0603BRD0766K5L)
RES, 66.5 k, 0.1%, 0.1 W, 0603; Manufacturer: Yageo America; CompType: Resistor; Value: 66.5k; Res_ohm: 66500; Value_Code: 66k5; Tolerance_%: 0.1; Value2: 0.1W; VDC_V: 75; TempCo: 25 ppm/C; SizeArea_mm2: 1.28; SizeX_mm: 1.6; SizeY_mm: 0.8; SizeZ_mm: 1; EIA_Code: E192; U/M: EA; AEC Category: Q200
signal-integrity model Resistor
simulation model Resistor
footprint 0603
footprint 0603M
footprint 0603L
footprint 0603_HV
footprint 0603S
pins: 1, 2

## RT0603BRD0766R5L
designator R?  ValueDisplayed: 66.5  (hidden comment: RT0603BRD0766R5L)
RES, 66.5, 0.1%, 0.1 W, 0603; Manufacturer: Yageo America; CompType: Resistor; Value: 66.5; Value_Code: 66R5; Tolerance_%: 0.1; Value2: 0.1W; VDC_V: 75; TempCo: 25 ppm/C; SizeArea_mm2: 1.28; SizeX_mm: 1.6; SizeY_mm: 0.8; SizeZ_mm: 1; EIA_Code: E192; U/M: EA; AEC Category: Q200
signal-integrity model Resistor
simulation model Resistor
footprint 0603
footprint 0603M
footprint 0603L
footprint 0603_HV
footprint 0603S
pins: 1, 2

## RT0603BRD0767K3L
designator R?  ValueDisplayed: 67.3k  (hidden comment: RT0603BRD0767K3L)
RES, 67.3 k, 0.1%, 0.1 W, 0603; Manufacturer: Yageo America; CompType: Resistor; Value: 67.3k; Res_ohm: 67300; Value_Code: 67k3; Tolerance_%: 0.1; Value2: 0.1W; VDC_V: 75; TempCo: 25 ppm/C; SizeArea_mm2: 1.28; SizeX_mm: 1.6; SizeY_mm: 0.8; SizeZ_mm: 1; EIA_Code: E192; U/M: EA; AEC Category: Q200
signal-integrity model Resistor
simulation model Resistor
footprint 0603
footprint 0603M
footprint 0603L
footprint 0603_HV
footprint 0603S
pins: 1, 2

## RT0603BRD0767R3L
designator R?  ValueDisplayed: 67.3  (hidden comment: RT0603BRD0767R3L)
RES, 67.3, 0.1%, 0.1 W, 0603; Manufacturer: Yageo America; CompType: Resistor; Value: 67.3; Value_Code: 67R3; Tolerance_%: 0.1; Value2: 0.1W; VDC_V: 75; TempCo: 25 ppm/C; SizeArea_mm2: 1.28; SizeX_mm: 1.6; SizeY_mm: 0.8; SizeZ_mm: 1; EIA_Code: E192; U/M: EA; AEC Category: Q200
signal-integrity model Resistor
simulation model Resistor
footprint 0603
footprint 0603M
footprint 0603L
footprint 0603_HV
footprint 0603S
pins: 1, 2

## RT0603BRD0768K1L
designator R?  ValueDisplayed: 68.1k  (hidden comment: RT0603BRD0768K1L)
RES, 68.1 k, 0.1%, 0.1 W, 0603; Manufacturer: Yageo America; CompType: Resistor; Value: 68.1k; Res_ohm: 68100; Value_Code: 68k1; Tolerance_%: 0.1; Value2: 0.1W; VDC_V: 75; TempCo: 25 ppm/C; SizeArea_mm2: 1.28; SizeX_mm: 1.6; SizeY_mm: 0.8; SizeZ_mm: 1; EIA_Code: E192; U/M: EA; AEC Category: Q200
signal-integrity model Resistor
simulation model Resistor
footprint 0603
footprint 0603M
footprint 0603L
footprint 0603_HV
footprint 0603S
pins: 1, 2

## RT0603BRD0768R1L
designator R?  ValueDisplayed: 68.1  (hidden comment: RT0603BRD0768R1L)
RES, 68.1, 0.1%, 0.1 W, 0603; Manufacturer: Yageo America; CompType: Resistor; Value: 68.1; Value_Code: 68R1; Tolerance_%: 0.1; Value2: 0.1W; VDC_V: 75; TempCo: 25 ppm/C; SizeArea_mm2: 1.28; SizeX_mm: 1.6; SizeY_mm: 0.8; SizeZ_mm: 1; EIA_Code: E192; U/M: EA; AEC Category: Q200
signal-integrity model Resistor
simulation model Resistor
footprint 0603
footprint 0603M
footprint 0603L
footprint 0603_HV
footprint 0603S
pins: 1, 2

## RT0603BRD0769K8L
designator R?  ValueDisplayed: 69.8k  (hidden comment: RT0603BRD0769K8L)
RES, 69.8 k, 0.1%, 0.1 W, 0603; Manufacturer: Yageo America; CompType: Resistor; Value: 69.8k; Res_ohm: 69800; Value_Code: 69k8; Tolerance_%: 0.1; Value2: 0.1W; VDC_V: 75; TempCo: 25 ppm/C; SizeArea_mm2: 1.28; SizeX_mm: 1.6; SizeY_mm: 0.8; SizeZ_mm: 1; EIA_Code: E192; U/M: EA; AEC Category: Q200
signal-integrity model Resistor
simulation model Resistor
footprint 0603
footprint 0603M
footprint 0603L
footprint 0603_HV
footprint 0603S
pins: 1, 2

## RT0603BRD0769KL
designator R?  ValueDisplayed: 69.0k  (hidden comment: RT0603BRD0769KL)
RES, 69.0 k, 0.1%, 0.1 W, 0603; Manufacturer: Yageo America; CompType: Resistor; Value: 69.0k; Res_ohm: 69000; Value_Code: 69k0; Tolerance_%: 0.1; Value2: 0.1W; VDC_V: 75; TempCo: 25 ppm/C; SizeArea_mm2: 1.28; SizeX_mm: 1.6; SizeY_mm: 0.8; SizeZ_mm: 1; EIA_Code: E192; U/M: EA; AEC Category: Q200
signal-integrity model Resistor
simulation model Resistor
footprint 0603
footprint 0603M
footprint 0603L
footprint 0603_HV
footprint 0603S
pins: 1, 2

## RT0603BRD0769R8L
designator R?  ValueDisplayed: 69.8  (hidden comment: RT0603BRD0769R8L)
RES, 69.8, 0.1%, 0.1 W, 0603; Manufacturer: Yageo America; CompType: Resistor; Value: 69.8; Value_Code: 69R8; Tolerance_%: 0.1; Value2: 0.1W; VDC_V: 75; TempCo: 25 ppm/C; SizeArea_mm2: 1.28; SizeX_mm: 1.6; SizeY_mm: 0.8; SizeZ_mm: 1; EIA_Code: E192; U/M: EA; AEC Category: Q200
signal-integrity model Resistor
simulation model Resistor
footprint 0603
footprint 0603M
footprint 0603L
footprint 0603_HV
footprint 0603S
pins: 1, 2

## RT0603BRD0769RL
designator R?  ValueDisplayed: 69.0  (hidden comment: RT0603BRD0769RL)
RES, 69.0, 0.1%, 0.1 W, 0603; Manufacturer: Yageo America; CompType: Resistor; Value: 69.0; Res_ohm: 69; Value_Code: 69R0; Tolerance_%: 0.1; Value2: 0.1W; VDC_V: 75; TempCo: 25 ppm/C; SizeArea_mm2: 1.28; SizeX_mm: 1.6; SizeY_mm: 0.8; SizeZ_mm: 1; EIA_Code: E192; U/M: EA; AEC Category: Q200
signal-integrity model Resistor
simulation model Resistor
footprint 0603
footprint 0603M
footprint 0603L
footprint 0603_HV
footprint 0603S
pins: 1, 2

## RT0603BRD0770K6L
designator R?  ValueDisplayed: 70.6k  (hidden comment: RT0603BRD0770K6L)
RES, 70.6 k, 0.1%, 0.1 W, 0603; Manufacturer: Yageo America; CompType: Resistor; Value: 70.6k; Res_ohm: 70600; Value_Code: 70k6; Tolerance_%: 0.1; Value2: 0.1W; VDC_V: 75; TempCo: 25 ppm/C; SizeArea_mm2: 1.28; SizeX_mm: 1.6; SizeY_mm: 0.8; SizeZ_mm: 1; EIA_Code: E192; U/M: EA; AEC Category: Q200
signal-integrity model Resistor
simulation model Resistor
footprint 0603
footprint 0603M
footprint 0603L
footprint 0603_HV
footprint 0603S
pins: 1, 2

## RT0603BRD0770R6L
designator R?  ValueDisplayed: 70.6  (hidden comment: RT0603BRD0770R6L)
RES, 70.6, 0.1%, 0.1 W, 0603; Manufacturer: Yageo America; CompType: Resistor; Value: 70.6; Value_Code: 70R6; Tolerance_%: 0.1; Value2: 0.1W; VDC_V: 75; TempCo: 25 ppm/C; SizeArea_mm2: 1.28; SizeX_mm: 1.6; SizeY_mm: 0.8; SizeZ_mm: 1; EIA_Code: E192; U/M: EA; AEC Category: Q200
signal-integrity model Resistor
simulation model Resistor
footprint 0603
footprint 0603M
footprint 0603L
footprint 0603_HV
footprint 0603S
pins: 1, 2

## RT0603BRD0771K5L
designator R?  ValueDisplayed: 71.5k  (hidden comment: RT0603BRD0771K5L)
RES, 71.5 k, 0.1%, 0.1 W, 0603; Manufacturer: Yageo America; CompType: Resistor; Value: 71.5k; Res_ohm: 71500; Value_Code: 71k5; Tolerance_%: 0.1; Value2: 0.1W; VDC_V: 75; TempCo: 25 ppm/C; SizeArea_mm2: 1.28; SizeX_mm: 1.6; SizeY_mm: 0.8; SizeZ_mm: 1; EIA_Code: E192; U/M: EA; AEC Category: Q200
signal-integrity model Resistor
simulation model Resistor
footprint 0603
footprint 0603M
footprint 0603L
footprint 0603_HV
footprint 0603S
pins: 1, 2

## RT0603BRD0771R5L
designator R?  ValueDisplayed: 71.5  (hidden comment: RT0603BRD0771R5L)
RES, 71.5, 0.1%, 0.1 W, 0603; Manufacturer: Yageo America; CompType: Resistor; Value: 71.5; Value_Code: 71R5; Tolerance_%: 0.1; Value2: 0.1W; VDC_V: 75; TempCo: 25 ppm/C; SizeArea_mm2: 1.28; SizeX_mm: 1.6; SizeY_mm: 0.8; SizeZ_mm: 1; EIA_Code: E192; U/M: EA; AEC Category: Q200
signal-integrity model Resistor
simulation model Resistor
footprint 0603
footprint 0603M
footprint 0603L
footprint 0603_HV
footprint 0603S
pins: 1, 2

## RT0603BRD0772K3L
designator R?  ValueDisplayed: 72.3k  (hidden comment: RT0603BRD0772K3L)
RES, 72.3 k, 0.1%, 0.1 W, 0603; Manufacturer: Yageo America; CompType: Resistor; Value: 72.3k; Res_ohm: 72300; Value_Code: 72k3; Tolerance_%: 0.1; Value2: 0.1W; VDC_V: 75; TempCo: 25 ppm/C; SizeArea_mm2: 1.28; SizeX_mm: 1.6; SizeY_mm: 0.8; SizeZ_mm: 1; EIA_Code: E192; U/M: EA; AEC Category: Q200
signal-integrity model Resistor
simulation model Resistor
footprint 0603
footprint 0603M
footprint 0603L
footprint 0603_HV
footprint 0603S
pins: 1, 2

## RT0603BRD0772R3L
designator R?  ValueDisplayed: 72.3  (hidden comment: RT0603BRD0772R3L)
RES, 72.3, 0.1%, 0.1 W, 0603; Manufacturer: Yageo America; CompType: Resistor; Value: 72.3; Value_Code: 72R3; Tolerance_%: 0.1; Value2: 0.1W; VDC_V: 75; TempCo: 25 ppm/C; SizeArea_mm2: 1.28; SizeX_mm: 1.6; SizeY_mm: 0.8; SizeZ_mm: 1; EIA_Code: E192; U/M: EA; AEC Category: Q200
signal-integrity model Resistor
simulation model Resistor
footprint 0603
footprint 0603M
footprint 0603L
footprint 0603_HV
footprint 0603S
pins: 1, 2

## RT0603BRD0773K2L
designator R?  ValueDisplayed: 73.2k  (hidden comment: RT0603BRD0773K2L)
RES, 73.2 k, 0.1%, 0.1 W, 0603; Manufacturer: Yageo America; CompType: Resistor; Value: 73.2k; Res_ohm: 73200; Value_Code: 73k2; Tolerance_%: 0.1; Value2: 0.1W; VDC_V: 75; TempCo: 25 ppm/C; SizeArea_mm2: 1.28; SizeX_mm: 1.6; SizeY_mm: 0.8; SizeZ_mm: 1; EIA_Code: E192; U/M: EA; AEC Category: Q200
signal-integrity model Resistor
simulation model Resistor
footprint 0603
footprint 0603M
footprint 0603L
footprint 0603_HV
footprint 0603S
pins: 1, 2

## RT0603BRD0773R2L
designator R?  ValueDisplayed: 73.2  (hidden comment: RT0603BRD0773R2L)
RES, 73.2, 0.1%, 0.1 W, 0603; Manufacturer: Yageo America; CompType: Resistor; Value: 73.2; Value_Code: 73R2; Tolerance_%: 0.1; Value2: 0.1W; VDC_V: 75; TempCo: 25 ppm/C; SizeArea_mm2: 1.28; SizeX_mm: 1.6; SizeY_mm: 0.8; SizeZ_mm: 1; EIA_Code: E192; U/M: EA; AEC Category: Q200
signal-integrity model Resistor
simulation model Resistor
footprint 0603
footprint 0603M
footprint 0603L
footprint 0603_HV
footprint 0603S
pins: 1, 2

## RT0603BRD0774K1L
designator R?  ValueDisplayed: 74.1k  (hidden comment: RT0603BRD0774K1L)
RES, 74.1 k, 0.1%, 0.1 W, 0603; Manufacturer: Yageo America; CompType: Resistor; Value: 74.1k; Res_ohm: 74100; Value_Code: 74k1; Tolerance_%: 0.1; Value2: 0.1W; VDC_V: 75; TempCo: 25 ppm/C; SizeArea_mm2: 1.28; SizeX_mm: 1.6; SizeY_mm: 0.8; SizeZ_mm: 1; EIA_Code: E192; U/M: EA; AEC Category: Q200
signal-integrity model Resistor
simulation model Resistor
footprint 0603
footprint 0603M
footprint 0603L
footprint 0603_HV
footprint 0603S
pins: 1, 2

## RT0603BRD0774R1L
designator R?  ValueDisplayed: 74.1  (hidden comment: RT0603BRD0774R1L)
RES, 74.1, 0.1%, 0.1 W, 0603; Manufacturer: Yageo America; CompType: Resistor; Value: 74.1; Value_Code: 74R1; Tolerance_%: 0.1; Value2: 0.1W; VDC_V: 75; TempCo: 25 ppm/C; SizeArea_mm2: 1.28; SizeX_mm: 1.6; SizeY_mm: 0.8; SizeZ_mm: 1; EIA_Code: E192; U/M: EA; AEC Category: Q200
signal-integrity model Resistor
simulation model Resistor
footprint 0603
footprint 0603M
footprint 0603L
footprint 0603_HV
footprint 0603S
pins: 1, 2

## RT0603BRD0775K9L
designator R?  ValueDisplayed: 75.9k  (hidden comment: RT0603BRD0775K9L)
RES, 75.9 k, 0.1%, 0.1 W, 0603; Manufacturer: Yageo America; CompType: Resistor; Value: 75.9k; Res_ohm: 75900; Value_Code: 75k9; Tolerance_%: 0.1; Value2: 0.1W; VDC_V: 75; TempCo: 25 ppm/C; SizeArea_mm2: 1.28; SizeX_mm: 1.6; SizeY_mm: 0.8; SizeZ_mm: 1; EIA_Code: E192; U/M: EA; AEC Category: Q200
signal-integrity model Resistor
simulation model Resistor
footprint 0603
footprint 0603M
footprint 0603L
footprint 0603_HV
footprint 0603S
pins: 1, 2

## RT0603BRD0775KL
designator R?  ValueDisplayed: 75.0k  (hidden comment: RT0603BRD0775KL)
RES, 75.0 k, 0.1%, 0.1 W, 0603; Manufacturer: Yageo America; CompType: Resistor; Value: 75.0k; Res_ohm: 75000; Value_Code: 75k0; Tolerance_%: 0.1; Value2: 0.1W; VDC_V: 75; TempCo: 25 ppm/C; SizeArea_mm2: 1.28; SizeX_mm: 1.6; SizeY_mm: 0.8; SizeZ_mm: 1; EIA_Code: E192; U/M: EA; AEC Category: Q200
signal-integrity model Resistor
simulation model Resistor
footprint 0603
footprint 0603M
footprint 0603L
footprint 0603_HV
footprint 0603S
pins: 1, 2

## RT0603BRD0775R9L
designator R?  ValueDisplayed: 75.9  (hidden comment: RT0603BRD0775R9L)
RES, 75.9, 0.1%, 0.1 W, 0603; Manufacturer: Yageo America; CompType: Resistor; Value: 75.9; Value_Code: 75R9; Tolerance_%: 0.1; Value2: 0.1W; VDC_V: 75; TempCo: 25 ppm/C; SizeArea_mm2: 1.28; SizeX_mm: 1.6; SizeY_mm: 0.8; SizeZ_mm: 1; EIA_Code: E192; U/M: EA; AEC Category: Q200
signal-integrity model Resistor
simulation model Resistor
footprint 0603
footprint 0603M
footprint 0603L
footprint 0603_HV
footprint 0603S
pins: 1, 2

## RT0603BRD0775RL
designator R?  ValueDisplayed: 75.0  (hidden comment: RT0603BRD0775RL)
RES, 75.0, 0.1%, 0.1 W, 0603; Manufacturer: Yageo America; CompType: Resistor; Value: 75.0; Res_ohm: 75; Value_Code: 75R0; Tolerance_%: 0.1; Value2: 0.1W; TempCo: 25 ppm/C; SizeArea_mm2: 1.28; SizeX_mm: 1.6; SizeY_mm: 0.8; SizeZ_mm: 1; EIA_Code: E192; U/M: EA; AEC Category: Q200
signal-integrity model Resistor
simulation model Resistor
footprint 0603
footprint 0603M
footprint 0603L
footprint 0603_HV
footprint 0603S
pins: 1, 2

## RT0603BRD0776K8L
designator R?  ValueDisplayed: 76.8k  (hidden comment: RT0603BRD0776K8L)
RES, 76.8 k, 0.1%, 0.1 W, 0603; Manufacturer: Yageo America; CompType: Resistor; Value: 76.8k; Res_ohm: 76800; Value_Code: 76k8; Tolerance_%: 0.1; Value2: 0.1W; VDC_V: 75; TempCo: 25 ppm/C; SizeArea_mm2: 1.28; SizeX_mm: 1.6; SizeY_mm: 0.8; SizeZ_mm: 1; EIA_Code: E192; U/M: EA; AEC Category: Q200
signal-integrity model Resistor
simulation model Resistor
footprint 0603
footprint 0603M
footprint 0603L
footprint 0603_HV
footprint 0603S
pins: 1, 2

## RT0603BRD0776R8L
designator R?  ValueDisplayed: 76.8  (hidden comment: RT0603BRD0776R8L)
RES, 76.8, 0.1%, 0.1 W, 0603; Manufacturer: Yageo America; CompType: Resistor; Value: 76.8; Value_Code: 76R8; Tolerance_%: 0.1; Value2: 0.1W; VDC_V: 75; TempCo: 25 ppm/C; SizeArea_mm2: 1.28; SizeX_mm: 1.6; SizeY_mm: 0.8; SizeZ_mm: 1; EIA_Code: E192; U/M: EA; AEC Category: Q200
signal-integrity model Resistor
simulation model Resistor
footprint 0603
footprint 0603M
footprint 0603L
footprint 0603_HV
footprint 0603S
pins: 1, 2

## RT0603BRD0777K7L
designator R?  ValueDisplayed: 77.7k  (hidden comment: RT0603BRD0777K7L)
RES, 77.7 k, 0.1%, 0.1 W, 0603; Manufacturer: Yageo America; CompType: Resistor; Value: 77.7k; Res_ohm: 77700; Value_Code: 77k7; Tolerance_%: 0.1; Value2: 0.1W; VDC_V: 75; TempCo: 25 ppm/C; SizeArea_mm2: 1.28; SizeX_mm: 1.6; SizeY_mm: 0.8; SizeZ_mm: 1; EIA_Code: E192; U/M: EA; AEC Category: Q200
signal-integrity model Resistor
simulation model Resistor
footprint 0603
footprint 0603M
footprint 0603L
footprint 0603_HV
footprint 0603S
pins: 1, 2

## RT0603BRD0777R7L
designator R?  ValueDisplayed: 77.7  (hidden comment: RT0603BRD0777R7L)
RES, 77.7, 0.1%, 0.1 W, 0603; Manufacturer: Yageo America; CompType: Resistor; Value: 77.7; Value_Code: 77R7; Tolerance_%: 0.1; Value2: 0.1W; VDC_V: 75; TempCo: 25 ppm/C; SizeArea_mm2: 1.28; SizeX_mm: 1.6; SizeY_mm: 0.8; SizeZ_mm: 1; EIA_Code: E192; U/M: EA; AEC Category: Q200
signal-integrity model Resistor
simulation model Resistor
footprint 0603
footprint 0603M
footprint 0603L
footprint 0603_HV
footprint 0603S
pins: 1, 2

## RT0603BRD0778K7L
designator R?  ValueDisplayed: 78.7k  (hidden comment: RT0603BRD0778K7L)
RES, 78.7 k, 0.1%, 0.1 W, 0603; Manufacturer: Yageo America; CompType: Resistor; Value: 78.7k; Res_ohm: 78700; Value_Code: 78k7; Tolerance_%: 0.1; Value2: 0.1W; VDC_V: 75; TempCo: 25 ppm/C; SizeArea_mm2: 1.28; SizeX_mm: 1.6; SizeY_mm: 0.8; SizeZ_mm: 1; EIA_Code: E192; U/M: EA; AEC Category: Q200
signal-integrity model Resistor
simulation model Resistor
footprint 0603
footprint 0603M
footprint 0603L
footprint 0603_HV
footprint 0603S
pins: 1, 2

## RT0603BRD0778R7L
designator R?  ValueDisplayed: 78.7  (hidden comment: RT0603BRD0778R7L)
RES, 78.7, 0.1%, 0.1 W, 0603; Manufacturer: Yageo America; CompType: Resistor; Value: 78.7; Value_Code: 78R7; Tolerance_%: 0.1; Value2: 0.1W; VDC_V: 75; TempCo: 25 ppm/C; SizeArea_mm2: 1.28; SizeX_mm: 1.6; SizeY_mm: 0.8; SizeZ_mm: 1; EIA_Code: E192; U/M: EA; AEC Category: Q200
signal-integrity model Resistor
simulation model Resistor
footprint 0603
footprint 0603M
footprint 0603L
footprint 0603_HV
footprint 0603S
pins: 1, 2

## RT0603BRD0779K6L
designator R?  ValueDisplayed: 79.6k  (hidden comment: RT0603BRD0779K6L)
RES, 79.6 k, 0.1%, 0.1 W, 0603; Manufacturer: Yageo America; CompType: Resistor; Value: 79.6k; Res_ohm: 79600; Value_Code: 79k6; Tolerance_%: 0.1; Value2: 0.1W; VDC_V: 75; TempCo: 25 ppm/C; SizeArea_mm2: 1.28; SizeX_mm: 1.6; SizeY_mm: 0.8; SizeZ_mm: 1; EIA_Code: E192; U/M: EA; AEC Category: Q200
signal-integrity model Resistor
simulation model Resistor
footprint 0603
footprint 0603M
footprint 0603L
footprint 0603_HV
footprint 0603S
pins: 1, 2

## RT0603BRD0779R6L
designator R?  ValueDisplayed: 79.6  (hidden comment: RT0603BRD0779R6L)
RES, 79.6, 0.1%, 0.1 W, 0603; Manufacturer: Yageo America; CompType: Resistor; Value: 79.6; Value_Code: 79R6; Tolerance_%: 0.1; Value2: 0.1W; VDC_V: 75; TempCo: 25 ppm/C; SizeArea_mm2: 1.28; SizeX_mm: 1.6; SizeY_mm: 0.8; SizeZ_mm: 1; EIA_Code: E192; U/M: EA; AEC Category: Q200
signal-integrity model Resistor
simulation model Resistor
footprint 0603
footprint 0603M
footprint 0603L
footprint 0603_HV
footprint 0603S
pins: 1, 2

## RT0603BRD0780K6L
designator R?  ValueDisplayed: 80.6k  (hidden comment: RT0603BRD0780K6L)
RES, 80.6 k, 0.1%, 0.1 W, 0603; Manufacturer: Yageo America; CompType: Resistor; Value: 80.6k; Res_ohm: 80600; Value_Code: 80k6; Tolerance_%: 0.1; Value2: 0.1W; VDC_V: 75; TempCo: 25 ppm/C; SizeArea_mm2: 1.28; SizeX_mm: 1.6; SizeY_mm: 0.8; SizeZ_mm: 1; EIA_Code: E192; U/M: EA; AEC Category: Q200
signal-integrity model Resistor
simulation model Resistor
footprint 0603
footprint 0603M
footprint 0603L
footprint 0603_HV
footprint 0603S
pins: 1, 2

## RT0603BRD0780R6L
designator R?  ValueDisplayed: 80.6  (hidden comment: RT0603BRD0780R6L)
RES, 80.6, 0.1%, 0.1 W, 0603; Manufacturer: Yageo America; CompType: Resistor; Value: 80.6; Value_Code: 80R6; Tolerance_%: 0.1; Value2: 0.1W; VDC_V: 75; TempCo: 25 ppm/C; SizeArea_mm2: 1.28; SizeX_mm: 1.6; SizeY_mm: 0.8; SizeZ_mm: 1; EIA_Code: E192; U/M: EA; AEC Category: Q200
signal-integrity model Resistor
simulation model Resistor
footprint 0603
footprint 0603M
footprint 0603L
footprint 0603_HV
footprint 0603S
pins: 1, 2

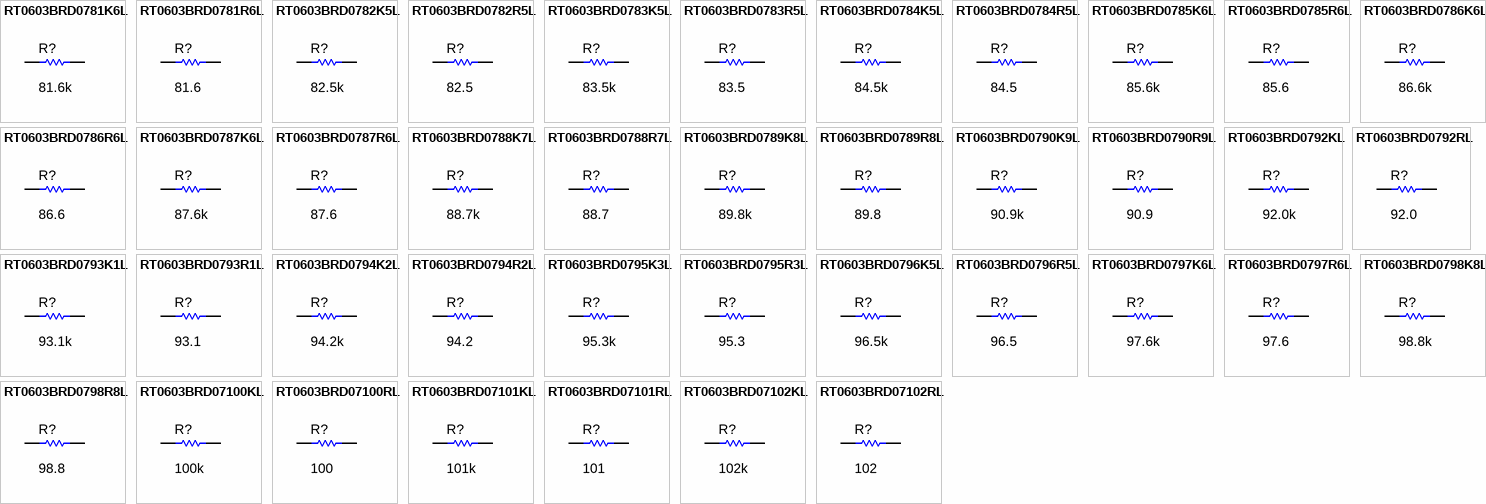
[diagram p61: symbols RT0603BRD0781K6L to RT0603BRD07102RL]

## RT0603BRD0781K6L
designator R?  ValueDisplayed: 81.6k  (hidden comment: RT0603BRD0781K6L)
RES, 81.6 k, 0.1%, 0.1 W, 0603; Manufacturer: Yageo America; CompType: Resistor; Value: 81.6k; Res_ohm: 81600; Value_Code: 81k6; Tolerance_%: 0.1; Value2: 0.1W; VDC_V: 75; TempCo: 25 ppm/C; SizeArea_mm2: 1.28; SizeX_mm: 1.6; SizeY_mm: 0.8; SizeZ_mm: 1; EIA_Code: E192; U/M: EA; AEC Category: Q200
signal-integrity model Resistor
simulation model Resistor
footprint 0603
footprint 0603M
footprint 0603L
footprint 0603_HV
footprint 0603S
pins: 1, 2

## RT0603BRD0781R6L
designator R?  ValueDisplayed: 81.6  (hidden comment: RT0603BRD0781R6L)
RES, 81.6, 0.1%, 0.1 W, 0603; Manufacturer: Yageo America; CompType: Resistor; Value: 81.6; Value_Code: 81R6; Tolerance_%: 0.1; Value2: 0.1W; VDC_V: 75; TempCo: 25 ppm/C; SizeArea_mm2: 1.28; SizeX_mm: 1.6; SizeY_mm: 0.8; SizeZ_mm: 1; EIA_Code: E192; U/M: EA; AEC Category: Q200
signal-integrity model Resistor
simulation model Resistor
footprint 0603
footprint 0603M
footprint 0603L
footprint 0603_HV
footprint 0603S
pins: 1, 2

## RT0603BRD0782K5L
designator R?  ValueDisplayed: 82.5k  (hidden comment: RT0603BRD0782K5L)
RES, 82.5 k, 0.1%, 0.1 W, 0603; Manufacturer: Yageo America; CompType: Resistor; Value: 82.5k; Res_ohm: 82500; Value_Code: 82k5; Tolerance_%: 0.1; Value2: 0.1W; VDC_V: 75; TempCo: 25 ppm/C; SizeArea_mm2: 1.28; SizeX_mm: 1.6; SizeY_mm: 0.8; SizeZ_mm: 1; EIA_Code: E192; U/M: EA; AEC Category: Q200
signal-integrity model Resistor
simulation model Resistor
footprint 0603
footprint 0603M
footprint 0603L
footprint 0603_HV
footprint 0603S
pins: 1, 2

## RT0603BRD0782R5L
designator R?  ValueDisplayed: 82.5  (hidden comment: RT0603BRD0782R5L)
RES, 82.5, 0.1%, 0.1 W, 0603; Manufacturer: Yageo America; CompType: Resistor; Value: 82.5; Value_Code: 82R5; Tolerance_%: 0.1; Value2: 0.1W; VDC_V: 75; TempCo: 25 ppm/C; SizeArea_mm2: 1.28; SizeX_mm: 1.6; SizeY_mm: 0.8; SizeZ_mm: 1; EIA_Code: E192; U/M: EA; AEC Category: Q200
signal-integrity model Resistor
simulation model Resistor
footprint 0603
footprint 0603M
footprint 0603L
footprint 0603_HV
footprint 0603S
pins: 1, 2

## RT0603BRD0783K5L
designator R?  ValueDisplayed: 83.5k  (hidden comment: RT0603BRD0783K5L)
RES, 83.5 k, 0.1%, 0.1 W, 0603; Manufacturer: Yageo America; CompType: Resistor; Value: 83.5k; Res_ohm: 83500; Value_Code: 83k5; Tolerance_%: 0.1; Value2: 0.1W; VDC_V: 75; TempCo: 25 ppm/C; SizeArea_mm2: 1.28; SizeX_mm: 1.6; SizeY_mm: 0.8; SizeZ_mm: 1; EIA_Code: E192; U/M: EA; AEC Category: Q200
signal-integrity model Resistor
simulation model Resistor
footprint 0603
footprint 0603M
footprint 0603L
footprint 0603_HV
footprint 0603S
pins: 1, 2

## RT0603BRD0783R5L
designator R?  ValueDisplayed: 83.5  (hidden comment: RT0603BRD0783R5L)
RES, 83.5, 0.1%, 0.1 W, 0603; Manufacturer: Yageo America; CompType: Resistor; Value: 83.5; Value_Code: 83R5; Tolerance_%: 0.1; Value2: 0.1W; VDC_V: 75; TempCo: 25 ppm/C; SizeArea_mm2: 1.28; SizeX_mm: 1.6; SizeY_mm: 0.8; SizeZ_mm: 1; EIA_Code: E192; U/M: EA; AEC Category: Q200
signal-integrity model Resistor
simulation model Resistor
footprint 0603
footprint 0603M
footprint 0603L
footprint 0603_HV
footprint 0603S
pins: 1, 2

## RT0603BRD0784K5L
designator R?  ValueDisplayed: 84.5k  (hidden comment: RT0603BRD0784K5L)
RES, 84.5 k, 0.1%, 0.1 W, 0603; Manufacturer: Yageo America; CompType: Resistor; Value: 84.5k; Res_ohm: 84500; Value_Code: 84k5; Tolerance_%: 0.1; Value2: 0.1W; VDC_V: 75; TempCo: 25 ppm/C; SizeArea_mm2: 1.28; SizeX_mm: 1.6; SizeY_mm: 0.8; SizeZ_mm: 1; EIA_Code: E192; U/M: EA; AEC Category: Q200
signal-integrity model Resistor
simulation model Resistor
footprint 0603
footprint 0603M
footprint 0603L
footprint 0603_HV
footprint 0603S
pins: 1, 2

## RT0603BRD0784R5L
designator R?  ValueDisplayed: 84.5  (hidden comment: RT0603BRD0784R5L)
RES, 84.5, 0.1%, 0.1 W, 0603; Manufacturer: Yageo America; CompType: Resistor; Value: 84.5; Value_Code: 84R5; Tolerance_%: 0.1; Value2: 0.1W; VDC_V: 75; TempCo: 25 ppm/C; SizeArea_mm2: 1.28; SizeX_mm: 1.6; SizeY_mm: 0.8; SizeZ_mm: 1; EIA_Code: E192; U/M: EA; AEC Category: Q200
signal-integrity model Resistor
simulation model Resistor
footprint 0603
footprint 0603M
footprint 0603L
footprint 0603_HV
footprint 0603S
pins: 1, 2

## RT0603BRD0785K6L
designator R?  ValueDisplayed: 85.6k  (hidden comment: RT0603BRD0785K6L)
RES, 85.6 k, 0.1%, 0.1 W, 0603; Manufacturer: Yageo America; CompType: Resistor; Value: 85.6k; Res_ohm: 85600; Value_Code: 85k6; Tolerance_%: 0.1; Value2: 0.1W; VDC_V: 75; TempCo: 25 ppm/C; SizeArea_mm2: 1.28; SizeX_mm: 1.6; SizeY_mm: 0.8; SizeZ_mm: 1; EIA_Code: E192; U/M: EA; AEC Category: Q200
signal-integrity model Resistor
simulation model Resistor
footprint 0603
footprint 0603M
footprint 0603L
footprint 0603_HV
footprint 0603S
pins: 1, 2

## RT0603BRD0785R6L
designator R?  ValueDisplayed: 85.6  (hidden comment: RT0603BRD0785R6L)
RES, 85.6, 0.1%, 0.1 W, 0603; Manufacturer: Yageo America; CompType: Resistor; Value: 85.6; Value_Code: 85R6; Tolerance_%: 0.1; Value2: 0.1W; VDC_V: 75; TempCo: 25 ppm/C; SizeArea_mm2: 1.28; SizeX_mm: 1.6; SizeY_mm: 0.8; SizeZ_mm: 1; EIA_Code: E192; U/M: EA; AEC Category: Q200
signal-integrity model Resistor
simulation model Resistor
footprint 0603
footprint 0603M
footprint 0603L
footprint 0603_HV
footprint 0603S
pins: 1, 2

## RT0603BRD0786K6L
designator R?  ValueDisplayed: 86.6k  (hidden comment: RT0603BRD0786K6L)
RES, 86.6 k, 0.1%, 0.1 W, 0603; Manufacturer: Yageo America; CompType: Resistor; Value: 86.6k; Res_ohm: 86600; Value_Code: 86k6; Tolerance_%: 0.1; Value2: 0.1W; VDC_V: 75; TempCo: 25 ppm/C; SizeArea_mm2: 1.28; SizeX_mm: 1.6; SizeY_mm: 0.8; SizeZ_mm: 1; EIA_Code: E192; U/M: EA; AEC Category: Q200
signal-integrity model Resistor
simulation model Resistor
footprint 0603
footprint 0603M
footprint 0603L
footprint 0603_HV
footprint 0603S
pins: 1, 2

## RT0603BRD0786R6L
designator R?  ValueDisplayed: 86.6  (hidden comment: RT0603BRD0786R6L)
RES, 86.6, 0.1%, 0.1 W, 0603; Manufacturer: Yageo America; CompType: Resistor; Value: 86.6; Value_Code: 86R6; Tolerance_%: 0.1; Value2: 0.1W; VDC_V: 75; TempCo: 25 ppm/C; SizeArea_mm2: 1.28; SizeX_mm: 1.6; SizeY_mm: 0.8; SizeZ_mm: 1; EIA_Code: E192; U/M: EA; AEC Category: Q200
signal-integrity model Resistor
simulation model Resistor
footprint 0603
footprint 0603M
footprint 0603L
footprint 0603_HV
footprint 0603S
pins: 1, 2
